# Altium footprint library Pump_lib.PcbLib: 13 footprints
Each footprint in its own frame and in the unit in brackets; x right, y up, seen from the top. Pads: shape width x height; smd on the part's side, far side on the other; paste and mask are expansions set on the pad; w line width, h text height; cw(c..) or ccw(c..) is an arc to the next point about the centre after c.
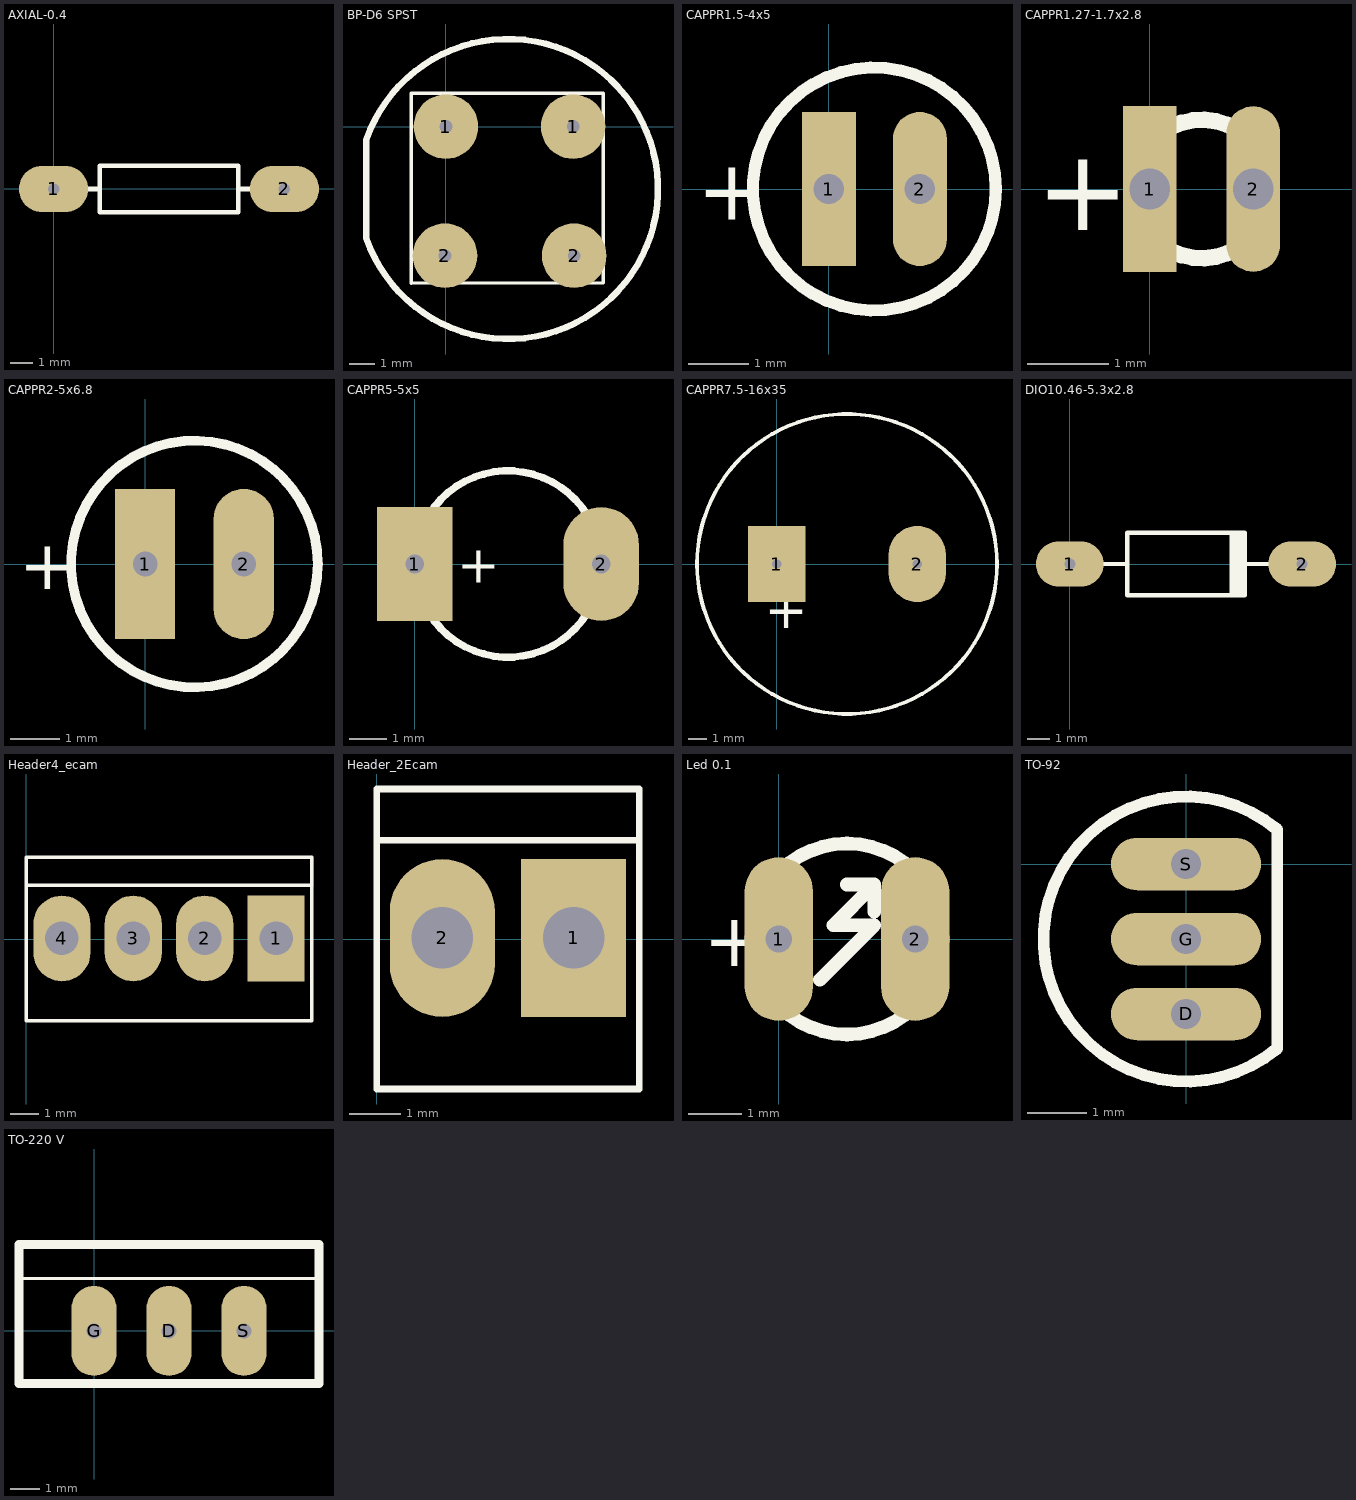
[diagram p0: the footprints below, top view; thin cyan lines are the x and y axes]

## AXIAL-0.4 [mil] "Resistor; 2 Leads"
height 80
pads (2):
  oval 120x80 hole 19.68: 1(0,0) 2(400,0)
Top Overlay:
  lines w7.87: 40,0 80,0 ; 320,0 360,0 ; 80,-40 80,40 320,40 320,-40 80,-40

## BP-D6 SPST [mm] "SPST Momentary Key Switches"
height 11.5
pads (4):
  round 2.54 hole 0.5: 1(0,0) 1(5.004,0) 2(-0.038,-5.08) 2(5.042,-5.08)
Mid-Layer 1:
  lines w1.27: -0.038,-5.08 5.042,-5.08 ; 0,0 5.004,0
Top Overlay:
  lines w0.127: -1.363,-6.162 -1.363,1.313 6.187,1.313 6.185,-6.156 -1.363,-6.162
  lines w0.254: -3.139,-4.377 ccw(c2.441,-2.455) -3.139,-0.534 -3.139,-4.277

## CAPPR1.5-4x5 [mm] "Capacitor, Electrolytic, Radial; Body 4 x 5 mm (Dia.xH typ); Pin Spacing 1.5 mm (typ)"
pads (2):
  rect 0.889x2.54 hole 0.5: 1(0,0)
  oval 0.889x2.54 hole 0.5: 2(1.5,0)
Top Overlay:
  circle w0.2: c0.75,0 r2
  text "+" at -2.171,-0.508 h1

## CAPPR1.27-1.7x2.8 [mil] "Capacitor, Radial, Tantalum; Body 1.7 x 2.8 mm (Dia.xH max); Pin Spacing 1.27 mm (typ)"
pads (2):
  rect 26x80 hole 19.68: 1(0,0)
  oval 26x80 hole 19.68: 2(50,0)
Top Overlay:
  circle w7.87: c25,0 r33.46
  text "+" at -55,-20 h39.37

## CAPPR2-5x6.8 [mil] "Capacitor, Electrolytic, Radial; Body 5 x 6.8 mm (Dia.xH typ); Pin Spacing 2 mm (typ)"
pads (2):
  rect 48x120 hole 19.68: 1(0,0)
  oval 48x120 hole 19.68: 2(78.74,0)
Top Overlay:
  circle w7.87: c39.37,0 r98.43
  text "+" at -100.63,-20 h39.37

## CAPPR5-5x5 [mil] "Capacitor, Electrolytic, Radial; Body 5 x 5 mm (Dia.xH typ); Pin Spacing 5 mm (typ)"
pads (2):
  rect 80x120 hole 19.68: 1(0,0)
  oval 80x120 hole 19.68: 2(196.85,0)
Top Overlay:
  lines w7.87: 9.56,-42.32 ccw(c98.43,0) 187.75,-41.33 ; 9.56,42.32 cw(c98.43,0) 187.75,41.33
  text "+" at 45,-20 h39.37

## CAPPR7.5-16x35 [mil] "Capacitor, Electrolytic, Radial; Body 16 x 35 mm (Dia.xH typ); Pin Spacing 7.5 mm (typ)"
pads (2):
  rect 120x160 hole 19.68: 1(0,0)
  oval 120x160 hole 19.68: 2(295.28,0)
Top Overlay:
  circle w7.87: c147.64,0 r314.96
  text "+" at -25,-135 h78.74

## DIO10.46-5.3x2.8 [mil] "Diode, Axial; Body 5.2 x 2.7 mm (LxDia. max), Lead Dia. 0.86 mm (max)"
height 110.24
pads (2):
  oval 120x80 hole 19.68: 1(0,0) 2(411.81,0)
Top Overlay:
  rectangle: 282.68,-55.12 314.17,55.12
  lines w7.87: 25,0 101.57,0 ; 305,0 385,0 ; 310.24,-55.12 101.57,-55.12 101.57,55.12 310.24,55.12

## Header4_ecam [mil]
pads (4):
  rect 80x120 hole 46.85: 1(350,0.79)
  oval 80x120 hole 46.85: 2(250,0.79) 3(150,0.79) 4(50,0.79)
Top Overlay:
  lines w5: 0,75 400,75 ; 0,-114.17 400,-114.17 400,114.17 0,114.17 0,-114.17
Mechanical 4:
  circle w7.87: c350,0 r3.94
  circle w7.87: c350,0 r3.94
  lines w5: 400,74.8 400,114.17

## Header_2Ecam [mil]
pads (2):
  rect 80x120 hole 46.85: 1(150,0.79)
  oval 80x120 hole 46.85: 2(50,0.79)
Top Overlay:
  lines w5: 0,75 200,75 ; 0,-114.17 0,114.17 200,114.17 200,0 200,-114.17 0,-114.17

## Led 0.1 [mil] "Led Verticale"
height 314.96
pads (2):
  oval 50x120 hole 19.68: 1(0,0) 2(100,0)
Top Overlay:
  circle w10: c50,0 r70
  lines w10: 30,-30 70,10 40,10 70,40 ; 50,40 70,40 ; 70,20 70,40
  text "+" at -55,-20 h39.37

## TO-92 [mil] "TO, Flat Index; 3 In-Line, Axial Leads; Body Dia. 4.6mm; Leads 0.48 x 0.43 mm (max) NOT ECAM RULES"
height 195
pads (3):
  oval 100x35 hole 19.68: D(0,-100) G(0,-50) S(0,0)
Top Overlay:
  lines w7.87: 60.82,-122.98 cw(c0,-50) 60.82,22.98 60.82,-122.98

## TO-220 V [mil] "TO-220 Vertical"
height 787.4
pads (3):
  oval 60x120 hole 19.68: D(100,0) G(0,0) S(200,0)
Top Overlay:
  lines w4: -100,70 300,70
  lines w12: -100,-70 -100,70 -100,115 300,115 300,70 300,-70 -100,-70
